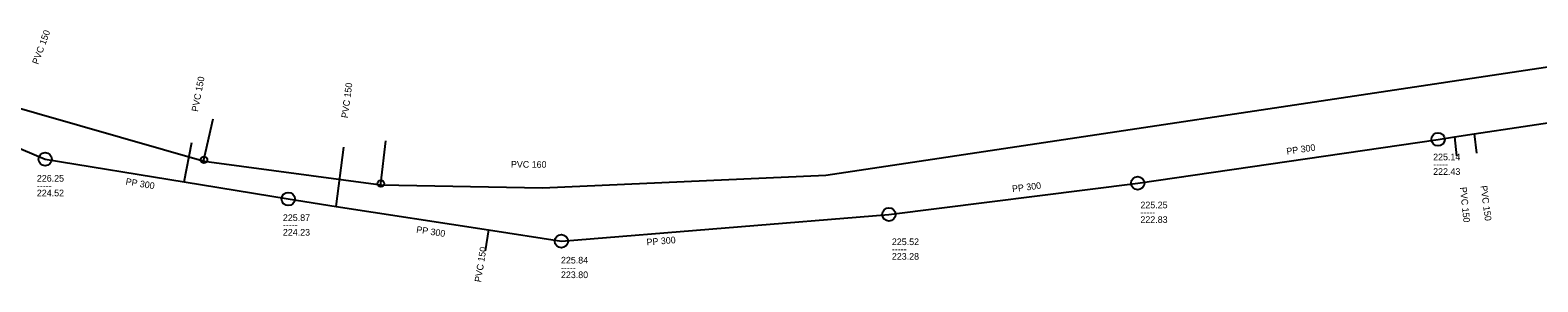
# Model space of a CAD drawing. Extents: x -771212 to -769571, y -1050452 to -1050119.
# Drawn here: x -770689.8 to -770462.8, y -1050353.4 to -1050315.5 of the extents above; entities that cross this region are included whole.
import ezdxf

# ---------------------------------------------------------------- set-up
doc = ezdxf.new("R2010")
doc.units = 0
doc.layers.add('Level 0', color=7, linetype='Continuous')

msp = doc.modelspace()

# ---------------------------------------------------------------- linework, layer by layer
at = {"layer": 'Level 0'}
for p, q in [((-770441.37, -1050318.11), (-770569.94, -1050337.38)), ((-770663.54, -1050335.3), (-770698.44, -1050325.32)), ((-770472.35, -1050331.14), (-770438.88, -1050326.12)), ((-770663.58, -1050335.03), (-770662.18, -1050328.88)), ((-770477.79, -1050331.96), (-770475.33, -1050331.59)), ((-770475.33, -1050331.59), (-770472.35, -1050331.14)), ((-770475.33, -1050331.59), (-770475.04, -1050334.42)), ((-770472.35, -1050331.14), (-770471.98, -1050334.02)), ((-770692.81, -1050332.69), (-770687.49, -1050334.94)), ((-770666.56, -1050338.37), (-770665.43, -1050332.46)), ((-770643.7, -1050342.05), (-770642.53, -1050333.16)), ((-770636.97, -1050338.6), (-770636.21, -1050332.18)), ((-770523.01, -1050338.56), (-770477.79, -1050331.96)), ((-770687.49, -1050334.94), (-770666.56, -1050338.37)), ((-770663.54, -1050335.3), (-770663.58, -1050335.03)), ((-770636.98, -1050338.86), (-770663.54, -1050335.3)), ((-770666.56, -1050338.37), (-770650.89, -1050340.94)), ((-770636.98, -1050338.86), (-770636.97, -1050338.6)), ((-770569.94, -1050337.38), (-770612.64, -1050339.33)), ((-770560.46, -1050343.26), (-770523.01, -1050338.56)), ((-770650.89, -1050340.94), (-770643.7, -1050342.05)), ((-770612.64, -1050339.33), (-770636.98, -1050338.86)), ((-770643.7, -1050342.05), (-770620.77, -1050345.59)), ((-770609.77, -1050347.29), (-770560.46, -1050343.26)), ((-770620.77, -1050345.59), (-770621.27, -1050348.73)), ((-770620.77, -1050345.59), (-770609.77, -1050347.29))]:
    msp.add_line(p, q, dxfattribs=at)
for centre, radius in [((-770477.79, -1050331.96), 1), ((-770687.49, -1050334.94), 1), ((-770663.58, -1050335.03), 0.5), ((-770636.97, -1050338.6), 0.5), ((-770523.01, -1050338.56), 1), ((-770650.89, -1050340.94), 1), ((-770560.46, -1050343.26), 1), ((-770609.77, -1050347.29), 1)]:
    msp.add_circle(centre, radius, dxfattribs=at)

# ---------------------------------------------------------------- texts
for s, rotation, p in [('PVC 150', 69.919, (-770688.55, -1050320.76)), ('PVC 150', 79.176, (-770664.49, -1050327.86)), ('PVC 150', 82.502, (-770641.93, -1050328.81)), ('PP 300', 8.304, (-770500.54, -1050334.27)), ('PVC 160', 359.66, (-770617.37, -1050336.22)), ('PP 300', 350.686, (-770675.43, -1050338.77)), ('PP 300', 7.153, (-770541.86, -1050339.92)), ('PVC 150', 275.851, (-770474.5, -1050339.19)), ('PVC 150', 277.321, (-770471.4, -1050338.98)), ('PP 300', 351.224, (-770631.67, -1050346)), ('PP 300', 4.672, (-770596.91, -1050347.94)), ('PVC 150', 80.952, (-770621.87, -1050353.52))]:
    msp.add_text(s, height=1, rotation=rotation, dxfattribs=at).set_placement(p)
for s, p in [('225.14', (-770478.53, -1050335.11)), ('-----', (-770478.53, -1050336.21)), ('222.43', (-770478.53, -1050337.31)), ('226.25', (-770688.74, -1050338.33)), ('-----', (-770688.74, -1050339.43)), ('224.52', (-770688.74, -1050340.53)), ('225.87', (-770651.7, -1050344.25)), ('-----', (-770522.6, -1050343.44)), ('225.25', (-770522.6, -1050342.34)), ('-----', (-770651.7, -1050345.35)), ('224.23', (-770651.7, -1050346.45)), ('222.83', (-770522.6, -1050344.54)), ('225.52', (-770560.02, -1050347.88)), ('225.84', (-770609.84, -1050350.65)), ('-----', (-770560.02, -1050348.98)), ('223.28', (-770560.02, -1050350.08)), ('-----', (-770609.84, -1050351.75)), ('223.80', (-770609.84, -1050352.85))]:
    msp.add_text(s, height=1, dxfattribs=at).set_placement(p)

doc.saveas('drawing.dxf')
